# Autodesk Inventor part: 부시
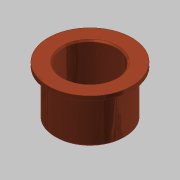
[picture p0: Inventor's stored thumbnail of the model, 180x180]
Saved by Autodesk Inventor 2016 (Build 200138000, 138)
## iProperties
Created: 2015-10
Part Number: 부시
Document SubType Name: Modeling
Designer: mdu
Density: 7.86 g/cm^3
Material: 강철, 연강
Mass: 246.97 g
Surface Area: 129.264 cm^2
Volume: 31.4212 cm^3
Appearance: 구리 - 새틴
Author: mdu
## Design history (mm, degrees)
sketch "스케치1"
  geometry: C1 r 31 at (0, 0) reference; C2 r 25 at (0, 0) reference; C3 r 30 at (0, 0) reference; 1 further point
  node "참조1"
  node "참조2"
  node "참조4"
extrude "돌출1" new body sketch "스케치1" distance "d0" = 3; taper "d1" = 0 deg
extrude "돌출2" join sketch "스케치1" distance "d2" = 35; taper "d3" = 0 deg
chamfer "모따기1" distance "d6" = 1; stored, may be unused: second distance "d7" = 2, angle "d8" = 45 deg
sketch "스케치3"
  geometry: C1 r 19 at (0, 0); 1 further point
  constraints: 1 centre point, 1 coincident
  dimensions: "d13" = 38 diameter of C1
extrude "돌출4" cut sketch "스케치3" stored distance "d14" = 10; taper "d15" = 0 deg
chamfer "모따기3" distance "d16" = 1; stored, may be unused: second distance "d17" = 2, angle "d18" = 45 deg
node "솔리드1"
